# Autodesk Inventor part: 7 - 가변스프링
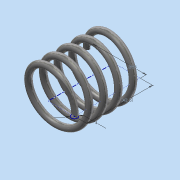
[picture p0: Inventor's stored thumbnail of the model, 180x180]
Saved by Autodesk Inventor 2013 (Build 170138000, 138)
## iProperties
Created: 2015-03
Part Number: 7 - 가변스프링
Material: 강철, 탄소
Document SubType Name: Modeling
Designer: Administrator
Density: 7.87 g/cm^3
Mass: 48.1117 g
Surface Area: 61.9996 cm^2
Volume: 6.11331 cm^3
Author: Administrator
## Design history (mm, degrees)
sketch "스케치1"
  geometry: L1 (0, 0)-(17.5, 0); L2 (17.5, 0)-(17.5, 43.5); L3 (17.5, 43.5)-(0, 43.5); L4 (0, 43.5)-(0, 0); C1 r 2 at (17.5, 0)
  constraints: 8 end point, 2 parallel, 1 centre point, 1 coincident, 1 horizontal, 1 perpendicular
  dimensions: "d0" = 4 diameter of C1; "d2" = 35 diameter of L2 L4; "d3" = 43.5 distance of L1.end L2.end (derived)
feature "코일1" sketch "스케치1" pitch "d4" = 10; turns "d6" = 4.5; dims "d5" = 43.5 (= d3), "d7" = 0, angle "d8" = 90 deg, angle "d9" = 90 deg, "d10" = 0, "d11" = 0
node "작업 평면1"
sketch "스케치2"
  geometry: L1 (-15.5, 0)-(-19.5, 0) reference; L2 (-15.5, 0)-(-19.5, 0) reference; 1 further point
  constraints: 2 horizontal alignment
extrude "돌출1" cut sketch "스케치2" stored distance "d13" = 10; taper "d14" = 0 deg
node "작업 평면2"
sketch "스케치3"
  geometry: L1 (19.5, 0)-(15.5, 0) reference; 1 further point
  constraints: 1 horizontal alignment
extrude "돌출2" cut sketch "스케치3" stored distance "d16" = 10; taper "d17" = 0 deg
node "솔리드1"
node "절단 모서리 투영1"
node "절단 모서리 투영2"
node "절단 모서리 투영3"
other parameters: "d12" = 0, "d15" = 43.5 (= d3)
